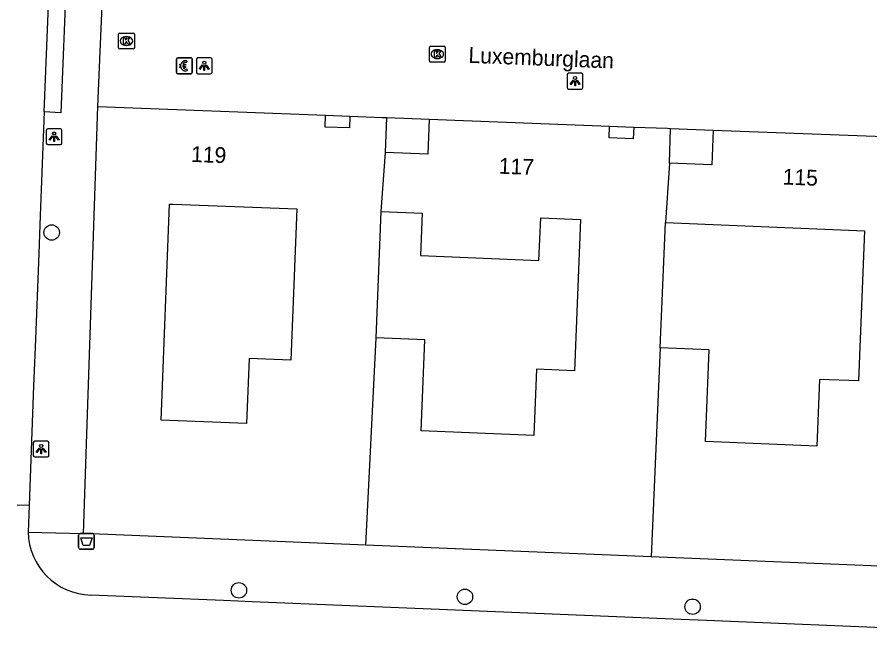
# Model space of a CAD drawing. Extents: x 160787 to 161428, y 386828 to 387483.
# Drawn here: x 161295.7 to 161349.8, y 386844 to 386882.9 of the extents above; entities that cross this region are included whole.
import ezdxf

# ---------------------------------------------------------------- set-up
doc = ezdxf.new("R2010")
doc.units = 0
for name, color, linetype in [('IMGEO_Afvalbak', 7, 'Continuous'), ('IMGEO_Betaalautomaat', 7, 'Continuous'), ('IMGEO_Boom', 7, 'Continuous'), ('IMGEO_Fietspad_open', 7, 'Continuous'), ('IMGEO_Kolk', 7, 'Continuous'), ('IMGEO_Lichtpunt', 7, 'Continuous'), ('IMGEO_Openbare_ruimte_label', 7, 'Continuous'), ('IMGEO_Pand', 7, 'Continuous'), ('IMGEO_Pand_nummerreeks', 7, 'Continuous'), ('IMGEO_Rijbaan_lokaal_open', 7, 'Continuous'), ('IMGEO_Voetpad_open', 7, 'Continuous')]:
    doc.layers.add(name, color=color, linetype=linetype)

msp = doc.modelspace()

# ---------------------------------------------------------------- linework, layer by layer
at = {"layer": 'IMGEO_Afvalbak'}
for p, q in [((161299.652, 386849.264), (161299.652, 386850.064)), ((161299.652, 386850.064), (161299.652, 386849.264)), ((161299.752, 386850.164), (161300.542, 386850.164)), ((161300.542, 386850.164), (161299.752, 386850.164)), ((161300.642, 386850.064), (161300.642, 386849.264)), ((161300.642, 386849.264), (161300.642, 386850.064)), ((161300.542, 386849.164), (161299.752, 386849.164)), ((161299.752, 386849.164), (161300.542, 386849.164))]:
    msp.add_line(p, q, dxfattribs=at)
msp.add_lwpolyline([(161299.795, 386849.878), (161300.499, 386849.878), (161300.35, 386849.408), (161299.944, 386849.408), (161299.795, 386849.878)], dxfattribs=at)
for centre, start, end in [((161299.752, 386850.064), 90, 180), ((161299.752, 386850.064), 90, 180), ((161300.542, 386850.064), 0, 90), ((161300.542, 386850.064), 360, 90), ((161299.752, 386849.264), 180, 270), ((161299.752, 386849.264), 180, 270), ((161300.542, 386849.264), 270, 0), ((161300.542, 386849.264), 270, 0)]:
    msp.add_arc(centre, 0.1, start, end, dxfattribs=at)
at = {"layer": 'IMGEO_Betaalautomaat'}
for p, q in [((161305.853, 386879.372), (161305.853, 386880.213)), ((161305.853, 386880.213), (161305.853, 386879.372)), ((161305.928, 386880.296), (161306.769, 386880.296)), ((161306.769, 386880.296), (161305.928, 386880.296)), ((161306.852, 386880.222), (161306.852, 386879.381)), ((161306.852, 386879.381), (161306.852, 386880.222)), ((161306.136, 386879.76), (161306.136, 386879.828)), ((161306.257, 386879.828), (161306.257, 386879.76)), ((161306.515, 386880.101), (161306.498, 386880.001)), ((161306.778, 386879.297), (161305.937, 386879.297)), ((161305.937, 386879.297), (161306.778, 386879.297)), ((161306.502, 386879.595), (161306.524, 386879.508))]:
    msp.add_line(p, q, dxfattribs=at)
for points in [[(161306.136, 386879.828), (161306.067, 386879.828), (161306.067, 386879.897), (161306.146, 386879.897)], [(161306.141, 386879.691), (161306.067, 386879.691), (161306.067, 386879.76), (161306.136, 386879.76)], [(161306.268, 386879.897), (161306.415, 386879.897), (161306.415, 386879.828), (161306.257, 386879.828)], [(161306.257, 386879.76), (161306.415, 386879.76), (161306.415, 386879.691), (161306.271, 386879.691)]]:
    msp.add_lwpolyline(points, dxfattribs=at)
for centre, radius, start, end in [((161305.931, 386880.219), 0.0779, 92.4484, 184.2845), ((161305.931, 386880.219), 0.0779, 92.4484, 184.2845), ((161306.775, 386880.219), 0.0779, 2.4484, 94.2845), ((161306.775, 386880.219), 0.0779, 2.4484, 94.2845), ((161306.402, 386879.746), 0.267, 191.8096, 297.0389), ((161306.429, 386879.821), 0.293, 73.014, 165.0139), ((161306.435, 386879.834), 0.179, 69.3236, 159.5683), ((161306.435, 386879.761), 0.179, 202.7625, 291.8693), ((161305.931, 386879.375), 0.0779, 182.4484, 274.2845), ((161305.931, 386879.375), 0.0779, 182.4484, 274.2845), ((161306.775, 386879.375), 0.0779, 272.4484, 4.2845), ((161306.775, 386879.375), 0.0779, 272.4484, 4.2845)]:
    msp.add_arc(centre, radius, start, end, dxfattribs=at)
at = {"layer": 'IMGEO_Boom'}
for centre in [(161297.941, 386869.233), (161309.81, 386846.56), (161324.136, 386846.15), (161338.563, 386845.521)]:
    msp.add_circle(centre, 0.489, dxfattribs=at)
at = {"layer": 'IMGEO_Fietspad_open'}
for points in [[(161296.507, 386851.934), (161296.448, 386850.254)], [(161355.379, 386843.987), (161354.487, 386844.024), (161352.646, 386844.1), (161339.454, 386844.646), (161337.845, 386844.713), (161325.048, 386845.242), (161323.038, 386845.325), (161310.655, 386845.837), (161308.832, 386845.913), (161300.435, 386846.26)]]:
    msp.add_lwpolyline(points, dxfattribs=at)
msp.add_arc((161300.518, 386850.33), 4.071, 181.0675, 268.832, dxfattribs=at)
at = {"layer": 'IMGEO_Kolk'}
for p, q in [((161302.182, 386880.943), (161302.182, 386881.795)), ((161302.257, 386881.869), (161303.109, 386881.869)), ((161303.183, 386881.795), (161303.183, 386880.943)), ((161302.67, 386881.649), (161302.695, 386881.649)), ((161303.109, 386880.869), (161302.257, 386880.869)), ((161302.693, 386881.089), (161302.668, 386881.089)), ((161321.885, 386880.109), (161321.885, 386880.961)), ((161321.96, 386881.035), (161322.812, 386881.035)), ((161322.373, 386880.815), (161322.398, 386880.815)), ((161322.886, 386880.961), (161322.886, 386880.109)), ((161322.396, 386880.255), (161322.371, 386880.255)), ((161322.812, 386880.035), (161321.96, 386880.035))]:
    msp.add_line(p, q, dxfattribs=at)
for points in [[(161302.182, 386880.943), (161302.182, 386881.795)], [(161302.257, 386881.869), (161303.109, 386881.869)], [(161303.183, 386881.795), (161303.183, 386880.943)], [(161302.503, 386881.569), (161302.626, 386881.569), (161302.626, 386881.418), (161302.756, 386881.569), (161302.92, 386881.569), (161302.774, 386881.418), (161302.927, 386881.169), (161302.775, 386881.169), (161302.69, 386881.333), (161302.626, 386881.266), (161302.626, 386881.169), (161302.503, 386881.169), (161302.503, 386881.569)], [(161303.109, 386880.869), (161302.257, 386880.869)], [(161321.885, 386880.109), (161321.885, 386880.961)], [(161321.96, 386881.035), (161322.812, 386881.035)], [(161322.206, 386880.735), (161322.329, 386880.735), (161322.329, 386880.584), (161322.459, 386880.735), (161322.623, 386880.735), (161322.477, 386880.584), (161322.63, 386880.335), (161322.478, 386880.335), (161322.393, 386880.499), (161322.329, 386880.432), (161322.329, 386880.335), (161322.206, 386880.335), (161322.206, 386880.735)], [(161322.886, 386880.961), (161322.886, 386880.109)], [(161322.812, 386880.035), (161321.96, 386880.035)]]:
    msp.add_lwpolyline(points, dxfattribs=at)
for centre, start, end in [((161302.259, 386881.793), 91.552, 178.448), ((161302.259, 386881.793), 91.552, 178.448), ((161303.107, 386881.793), 1.552, 88.448), ((161303.107, 386881.793), 1.552, 88.448), ((161302.259, 386880.945), 181.552, 268.448), ((161302.259, 386880.945), 181.552, 268.448), ((161303.107, 386880.945), 271.552, 358.448), ((161303.107, 386880.945), 271.552, 358.448), ((161321.962, 386880.959), 91.552, 178.448), ((161321.962, 386880.959), 91.552, 178.448), ((161322.81, 386880.959), 1.552, 88.448), ((161322.81, 386880.959), 1.552, 88.448), ((161321.962, 386880.111), 181.552, 268.448), ((161321.962, 386880.111), 181.552, 268.448), ((161322.81, 386880.111), 271.552, 358.448), ((161322.81, 386880.111), 271.552, 358.448)]:
    msp.add_arc(centre, 0.0765, start, end, dxfattribs=at)
for centre, major_axis, ratio, start_param, end_param in [((161302.669, 386881.369), (-0.387, 0.002), 0.722429, 4.712389, 7.853982), ((161302.694, 386881.369), (-0.39, 0.002), 0.717154, 1.570796, 4.712389), ((161322.372, 386880.535), (-0.387, 0.002), 0.722429, 4.712389, 7.853982), ((161322.397, 386880.535), (-0.39, 0.002), 0.717154, 1.570796, 4.712389)]:
    msp.add_ellipse(centre, major_axis=major_axis, ratio=ratio, start_param=start_param, end_param=end_param, dxfattribs=at)
at = {"layer": 'IMGEO_Lichtpunt'}
for p, q in [((161307.115, 386880.198), (161307.115, 386879.391)), ((161307.115, 386880.198), (161307.115, 386879.391)), ((161308.017, 386880.293), (161307.209, 386880.293)), ((161308.017, 386880.293), (161307.209, 386880.293)), ((161308.111, 386879.391), (161308.111, 386880.198)), ((161308.111, 386879.391), (161308.111, 386880.198)), ((161307.209, 386879.297), (161308.017, 386879.297)), ((161307.209, 386879.297), (161308.017, 386879.297)), ((161330.614, 386879.225), (161330.614, 386878.418)), ((161330.614, 386879.225), (161330.614, 386878.418)), ((161331.516, 386879.32), (161330.708, 386879.32)), ((161331.516, 386879.32), (161330.708, 386879.32)), ((161331.61, 386878.418), (161331.61, 386879.225)), ((161331.61, 386878.418), (161331.61, 386879.225)), ((161330.708, 386878.324), (161331.516, 386878.324)), ((161330.708, 386878.324), (161331.516, 386878.324)), ((161297.6, 386875.705), (161297.6, 386874.898)), ((161297.6, 386875.705), (161297.6, 386874.898)), ((161298.502, 386875.8), (161297.694, 386875.8)), ((161298.502, 386875.8), (161297.694, 386875.8)), ((161298.596, 386874.898), (161298.596, 386875.705)), ((161298.596, 386874.898), (161298.596, 386875.705)), ((161297.694, 386874.804), (161298.502, 386874.804)), ((161297.694, 386874.804), (161298.502, 386874.804)), ((161296.777, 386855.911), (161296.777, 386855.104)), ((161296.777, 386855.911), (161296.777, 386855.104)), ((161297.679, 386856.006), (161296.871, 386856.006)), ((161297.679, 386856.006), (161296.871, 386856.006)), ((161297.773, 386855.104), (161297.773, 386855.911)), ((161297.773, 386855.104), (161297.773, 386855.911)), ((161296.871, 386855.01), (161297.679, 386855.01)), ((161296.871, 386855.01), (161297.679, 386855.01))]:
    msp.add_line(p, q, dxfattribs=at)
for points in [[(161307.489, 386879.862), (161307.528, 386879.834), (161307.34, 386879.572), (161307.302, 386879.599), (161307.489, 386879.862)], [(161307.591, 386879.814), (161307.638, 386879.814), (161307.638, 386879.492), (161307.591, 386879.492), (161307.591, 386879.814)], [(161307.701, 386879.834), (161307.739, 386879.861), (161307.926, 386879.599), (161307.887, 386879.571), (161307.701, 386879.834)], [(161330.988, 386878.889), (161331.027, 386878.861), (161330.839, 386878.599), (161330.801, 386878.626), (161330.988, 386878.889)], [(161331.09, 386878.841), (161331.137, 386878.841), (161331.137, 386878.519), (161331.09, 386878.519), (161331.09, 386878.841)], [(161331.2, 386878.861), (161331.238, 386878.888), (161331.425, 386878.626), (161331.386, 386878.598), (161331.2, 386878.861)], [(161297.974, 386875.369), (161298.013, 386875.341), (161297.825, 386875.079), (161297.787, 386875.106), (161297.974, 386875.369)], [(161298.076, 386875.321), (161298.123, 386875.321), (161298.123, 386874.999), (161298.076, 386874.999), (161298.076, 386875.321)], [(161298.186, 386875.341), (161298.224, 386875.368), (161298.411, 386875.106), (161298.372, 386875.078), (161298.186, 386875.341)], [(161297.151, 386855.575), (161297.19, 386855.547), (161297.002, 386855.285), (161296.964, 386855.312), (161297.151, 386855.575)], [(161297.253, 386855.527), (161297.3, 386855.527), (161297.3, 386855.205), (161297.253, 386855.205), (161297.253, 386855.527)], [(161297.363, 386855.547), (161297.401, 386855.574), (161297.588, 386855.312), (161297.549, 386855.284), (161297.363, 386855.547)]]:
    msp.add_lwpolyline(points, dxfattribs=at)
for centre in [(161307.614, 386879.996), (161331.113, 386879.023), (161298.099, 386875.503), (161297.276, 386855.709)]:
    msp.add_circle(centre, 0.0994, dxfattribs=at)
for centre, start, end in [((161307.209, 386880.198), 90, 180), ((161307.209, 386880.198), 90, 180), ((161308.017, 386880.198), 0, 90), ((161308.017, 386880.198), 0, 90), ((161307.209, 386879.391), 180, 270), ((161307.209, 386879.391), 180, 270), ((161308.017, 386879.391), 270, 0), ((161308.017, 386879.391), 270, 360), ((161330.708, 386879.225), 90, 180), ((161330.708, 386879.225), 90, 180), ((161331.516, 386879.225), 0, 90), ((161331.516, 386879.225), 0, 90), ((161330.708, 386878.418), 180, 270), ((161330.708, 386878.418), 180, 270), ((161331.516, 386878.418), 270, 0), ((161331.516, 386878.418), 270, 360), ((161297.694, 386875.705), 90, 180), ((161297.694, 386875.705), 90, 180), ((161298.502, 386875.705), 0, 90), ((161298.502, 386875.705), 0, 90), ((161297.694, 386874.898), 180, 270), ((161297.694, 386874.898), 180, 270), ((161298.502, 386874.898), 270, 0), ((161298.502, 386874.898), 270, 360), ((161296.871, 386855.911), 90, 180), ((161296.871, 386855.911), 90, 180), ((161297.679, 386855.911), 0, 90), ((161297.679, 386855.911), 0, 90), ((161296.871, 386855.104), 180, 270), ((161296.871, 386855.104), 180, 270), ((161297.679, 386855.104), 270, 0), ((161297.679, 386855.104), 270, 360)]:
    msp.add_arc(centre, 0.0946, start, end, dxfattribs=at)
at = {"layer": 'IMGEO_Pand'}
for points in [[(161299.968, 386850.162), (161300.865, 386877.218)], [(161300.865, 386877.218), (161315.301, 386876.666)], [(161316.84, 386876.607), (161316.812, 386875.859), (161315.273, 386875.918), (161315.301, 386876.666)], [(161316.84, 386876.607), (161318.887, 386876.528), (161319.178, 386876.517)], [(161319.094, 386874.31), (161319.178, 386876.517)], [(161321.876, 386876.414), (161321.792, 386874.207), (161319.094, 386874.31)], [(161321.876, 386876.414), (161333.297, 386875.977)], [(161334.836, 386875.918), (161334.808, 386875.17), (161333.269, 386875.229), (161333.297, 386875.977)], [(161334.836, 386875.918), (161336.977, 386875.836), (161337.174, 386875.829)], [(161337.09, 386873.621), (161337.174, 386875.829)], [(161339.872, 386875.726), (161339.788, 386873.518), (161337.09, 386873.621)], [(161339.872, 386875.726), (161351.283, 386875.289)], [(161318.832, 386870.568), (161319.094, 386874.31)], [(161337.09, 386873.621), (161336.846, 386869.86)], [(161305.632, 386871.025), (161313.471, 386870.725), (161313.105, 386861.151), (161310.454, 386861.253), (161310.296, 386857.132), (161304.891, 386857.339), (161305.415, 386871.033), (161305.632, 386871.025)], [(161318.508, 386862.564), (161318.832, 386870.568)], [(161318.832, 386870.568), (161321.433, 386870.463), (161321.325, 386867.773), (161328.828, 386867.469), (161328.937, 386870.159), (161331.459, 386870.057), (161331.071, 386860.476), (161328.666, 386860.573), (161328.496, 386856.379), (161321.367, 386856.668), (161321.601, 386862.439), (161318.508, 386862.564)], [(161336.846, 386869.86), (161349.463, 386869.34), (161349.071, 386859.826), (161346.615, 386859.928), (161346.44, 386855.699), (161339.376, 386855.99), (161339.615, 386861.791), (161336.519, 386861.919)], [(161336.519, 386861.919), (161336.846, 386869.86)], [(161317.851, 386849.428), (161318.508, 386862.564)], [(161336.519, 386861.919), (161335.938, 386848.687)], [(161317.851, 386849.428), (161299.968, 386850.162)], [(161335.938, 386848.687), (161317.851, 386849.428)], [(161354.027, 386847.945), (161335.938, 386848.687)]]:
    msp.add_lwpolyline(points, dxfattribs=at)
at = {"layer": 'IMGEO_Rijbaan_lokaal_open'}
for points in [[(161300.865, 386877.218), (161301.242, 386886.141)], [(161297.462, 386876.869), (161297.831, 386885.751)], [(161297.462, 386876.869), (161297.211, 386870.31), (161297.119, 386867.903), (161296.891, 386861.949), (161296.798, 386859.523), (161296.507, 386851.934)], [(161315.301, 386876.666), (161316.84, 386876.607)], [(161319.178, 386876.517), (161321.876, 386876.414)], [(161333.297, 386875.977), (161334.836, 386875.918)], [(161337.174, 386875.829), (161339.872, 386875.726)], [(161296.507, 386851.934), (161295.749, 386851.961), (161295.749, 386851.961)]]:
    msp.add_lwpolyline(points, dxfattribs=at)
at = {"layer": 'IMGEO_Voetpad_open'}
for points in [[(161297.831, 386885.751), (161298.882, 386885.709), (161298.525, 386876.826), (161297.462, 386876.869)], [(161296.448, 386850.254), (161299.968, 386850.162)]]:
    msp.add_lwpolyline(points, dxfattribs=at)

# ---------------------------------------------------------------- texts
at = {"layer": 'IMGEO_Openbare_ruimte_label'}
msp.add_text('Luxemburglaan', height=1, rotation=357.7644, dxfattribs=at).set_placement((161324.345, 386879.986))
at = {"layer": 'IMGEO_Pand_nummerreeks'}
for s, rotation, p in [('119', 357.8102, (161306.763, 386873.71)), ('117', 357.8088, (161326.267, 386872.964)), ('115', 357.8068, (161344.258, 386872.276))]:
    msp.add_text(s, height=1, rotation=rotation, dxfattribs=at).set_placement(p)

doc.saveas('drawing.dxf')
